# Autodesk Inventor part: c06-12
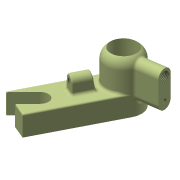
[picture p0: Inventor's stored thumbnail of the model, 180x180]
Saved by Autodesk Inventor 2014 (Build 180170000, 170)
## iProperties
Created: 2013-03
Part Number: c06-12
Material: Aluminum 6061
Document SubType Name: Modeling
Designer: Thom Tremblay
Density: 2.71 g/cm^3
Appearance: Zinc Chromate 2
Author: Thom Tremblay
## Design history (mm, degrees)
sketch "Sketch1"
  geometry: L1 (0, -12.5)-(60, -12.5); L2 (60, -12.5)-(60, 12.5); L3 (60, 12.5)-(0, 12.5); L4 (0, 12.5)-(0, -12.5); 2 further points
  constraints: 8 end point, 2 parallel, 1 coincident, 1 horizontal, 1 midpoint, 1 perpendicular
  dimensions: "d1" = 25 distance of L2.end L1.end; "d2" = 60 distance of L2.end L3.end
extrude "Base" new body sketch "Sketch1" distance "d3" = 14; taper "d4" = 0 deg
sketch "Sketch2"
  geometry: C1 r 12.5 at (0, 0); 1 further point
  constraints: 1 centre point, 1 coincident
extrude "Boss" join sketch "Sketch2" distance "d5" = 35; taper "d6" = 0 deg
sketch "Sketch3"
  geometry: L1 (-60, 12.5)-(-60, -12.5) reference; L2 (-60, -6)-(-60, 6); L3 (-43.948, 5.638)-(-60, 11.481); L4 (-48.052, -5.638)-(-60, -1.289); L5 (-60, 11.481)-(-60, -1.289); A1 r 6 centre (-46, 0) between (-43.948, 5.638) and (-48.052, -5.638); 2 further points
  constraints: 8 end point, 3 midpoint, 2 point on circle, 2 point on line, 2 tangent, 1 centre point, 1 collinear, 1 horizontal alignment, 1 parallel
  dimensions: "d8" = 12 diameter of A1; "d20" = 20 dimension on A1 L1; "d27" = 70 deg angle of L1 L3
extrude "Slot" cut sketch "Sketch3" stored distance "d9" = 24; taper "d10" = 0 deg
hole "Hole1" diameter "d13" = 11; stored, may be unused: countersink angle "d17" = 90 deg, drill point angle "d19" = 118 deg; dims "d11" = 10, "d12" = 10, "d14" = 6, "d15" = 18, "d16" = 11, "d18" = 8
fillet "Fillet1" dims "d26" = 8
node "Midplane between faces"
node "Normal to Edge at Point"
node "Offset Plane"
  node "Tangent Plane"
sketch "Sketch4"
  geometry: L1 (0, 0)-(-60, 0) reference; L2 (-14, 0)-(-18.341, 24.62)
  constraints: 2 end point, 1 point on line
  dimensions: "d21" = 25 distance of L2.start L2.end; "d22" = 80 deg angle of L1 L2; "d23" = 14 distance of L1.start L2.start
node "Plane at Angle on Sketch"
sketch "Sketch5"
  geometry: L1 (0, 0)-(-19.151, 16.07); L2 (0, 0)-(25, 0); C1 r 9 at (0, 0) reference; C2 r 5.5 at (0, 0) reference
  constraints: 4 end point, 1 equal length, 1 horizontal
  dimensions: "d24" = 25 distance of L1.start L1.end; "d25" = 140 deg angle of L2 L1
node "Plane using Sketch as Axis"
sketch "Sketch6"
  geometry: L1 (33, 0)-(8, 0); L2 (28, -5)-(13, -5); L3 (13, 5)-(28, 5); L4 (35, 9)-(35, -9) reference; A1 r 5 centre (28, 0) between (28, -5) and (28, 5); A2 r 5 centre (13, 0) between (13, 5) and (13, -5); 2 further points
  constraints: 8 end point, 6 point on circle, 4 tangent, 3 point on line, 2 centre point, 1 horizontal, 1 midpoint, 1 parallel
  dimensions: "d33" = 2 distance from line of L1.start L4; "d34" = 25 distance of L1.start L1.end; "d35" = 5 radius of A2
extrude "Extrusion4" join sketch "Sketch6" stored distance "d37" = 10; taper "d38" = 0 deg
sketch "Sketch7"
  geometry: L1 (-18.138, 14)-(-6.5, 14) reference; L2 (-16.5, 14)-(-16.5, 21); L3 (-8.5, 21)-(-8.5, 14); A1 r 4 centre (-12.5, 21) between (-8.5, 21) and (-16.5, 21); 2 further points
  constraints: 4 end point, 2 perpendicular, 2 point on circle, 2 point on line, 2 tangent, 1 centre point, 1 vertical alignment
  dimensions: "d31" = 7 distance of L3.start L3.end; "d32" = 4 radius of A1
extrude "Extrusion5" join sketch "Sketch7" stored distance "d39" = 10; taper "d40" = 0 deg
hole "Hole2" diameter "d43" = 3.242; stored, may be unused: countersink angle "d47" = 90 deg, drill point angle "d49" = 118 deg; dims "d41" = 10, "d42" = 10, "d44" = 6, "d45" = 4, "d46" = 2, "d48" = 8
hole "Hole3" diameter "d52" = 6; stored, may be unused: countersink angle "d58" = 90 deg, drill point angle "d60" = 118 deg; dims "d53" = 9, "d54" = 0.62479, "d55" = 5.98, "d56" = 4, "d57" = 2, "d59" = 8, "d61" = 10, "d62" = 10
hole "Hole4" diameter "d65" = 3.242; stored, may be unused: countersink angle "d69" = 90 deg, drill point angle "d71" = 118 deg; dims "d63" = 10, "d64" = 10, "d66" = 6.5, "d67" = 4, "d68" = 2, "d70" = 8
fillet "Fillet2" dims "d72" = 2, "d73" = 1
body "Solid1"
node "Plane at Angle"
other parameters: "d29" = 15, "d30" = 90 deg, "d74" = 30 deg
